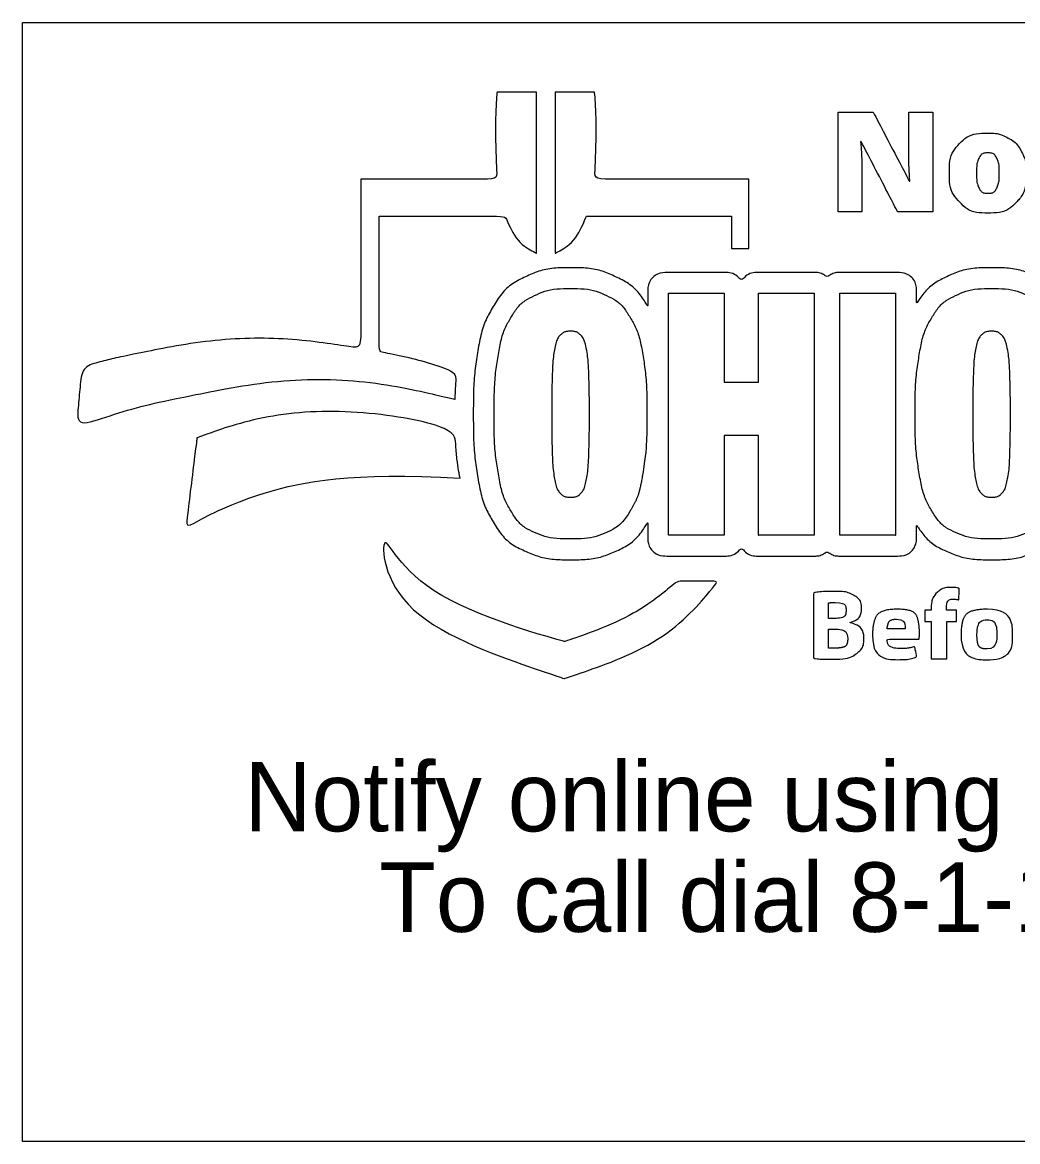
# Model space of a CAD drawing. Extents: x 0 to 34, y 0 to 22.
# Drawn here: x 1.992 to 3.998, y 2.74 to 4.995 of the extents above; entities that cross this region are included whole.
import ezdxf

# ---------------------------------------------------------------- set-up
doc = ezdxf.new("R2010")
doc.units = 0
doc.layers.add('Default', color=7, linetype='Continuous')
doc.layers.add('SH_Data', color=7, linetype='Continuous')

msp = doc.modelspace()

# ---------------------------------------------------------------- linework, layer by layer
at = {"layer": 'Default'}
for points, degree in [([(2.8645, 4.2355), (2.8645, 4.2355), (2.8644, 4.2355), (2.8644, 4.2355), (2.6966, 4.2753), (2.5082, 4.2791), (2.3129, 4.2392), (2.2394, 4.2241), (2.1686, 4.2034), (2.1007, 4.178), (2.1045, 4.2182), (2.1085, 4.2608), (2.1123, 4.301), (2.1442, 4.3099), (2.1765, 4.3182), (2.2095, 4.3249), (2.3719, 4.3581), (2.5295, 4.3609), (2.6744, 4.3379), (2.6744, 4.3379), (2.6744, 4.6788), (2.6744, 4.6788), (2.6744, 4.6788), (2.9488, 4.6788), (2.9488, 4.6788), (2.9438, 4.7876), (2.9488, 4.8545), (2.9488, 4.8545), (2.9488, 4.8545), (3.0286, 4.8545), (3.0286, 4.8545), (3.0286, 4.8545), (3.0286, 4.5298), (3.0286, 4.5298), (3.0286, 4.5298), (2.9887, 4.5504), (2.9652, 4.6045), (2.9652, 4.6045), (2.7111, 4.6045), (2.7111, 4.6045), (2.7111, 4.6045), (2.7111, 4.3314), (2.7111, 4.3314), (2.7654, 4.3211), (2.8178, 4.3071), (2.8678, 4.2896), (2.8661, 4.2729), (2.8651, 4.255), (2.8645, 4.2355)], 3), ([(3.1289, 4.6046), (3.1289, 4.6046), (3.129, 4.6046), (3.129, 4.6046), (3.1056, 4.5506), (3.0657, 4.5299), (3.0657, 4.5299), (3.0657, 4.5299), (3.0657, 4.8545), (3.0657, 4.8545), (3.0657, 4.8545), (3.1454, 4.8545), (3.1454, 4.8545), (3.1454, 4.8545), (3.1504, 4.7876), (3.1454, 4.6788), (3.1454, 4.6788), (3.4564, 4.6788), (3.4564, 4.6788), (3.4564, 4.6788), (3.4564, 4.5391), (3.4564, 4.5391), (3.4564, 4.5391), (3.4216, 4.5391), (3.4216, 4.5391), (3.4216, 4.5391), (3.4216, 4.6046), (3.4216, 4.6046), (3.4216, 4.6046), (3.1289, 4.6046), (3.1289, 4.6046)], 3), ([(3.827, 4.6136), (3.827, 4.6136), (3.827, 4.8142), (3.827, 4.8142), (3.827, 4.8142), (3.7787, 4.8142), (3.7787, 4.8142), (3.7787, 4.8142), (3.7787, 4.7235), (3.7787, 4.7235), (3.7787, 4.7112), (3.7793, 4.695), (3.7806, 4.6748), (3.7806, 4.6748), (3.7798, 4.6748), (3.7798, 4.6748), (3.7798, 4.6748), (3.7068, 4.8142), (3.7068, 4.8142), (3.7068, 4.8142), (3.636, 4.8142), (3.636, 4.8142), (3.636, 4.8142), (3.636, 4.6136), (3.636, 4.6136), (3.636, 4.6136), (3.684, 4.6136), (3.684, 4.6136), (3.684, 4.6136), (3.684, 4.704), (3.684, 4.704), (3.684, 4.7157), (3.6831, 4.7327), (3.6814, 4.7549), (3.6814, 4.7549), (3.6826, 4.7549), (3.6826, 4.7549), (3.6826, 4.7549), (3.7559, 4.6136), (3.7559, 4.6136), (3.7559, 4.6136), (3.827, 4.6136), (3.827, 4.6136)], 3), ([(4.0155, 4.6917), (4.0155, 4.7079), (4.0124, 4.722), (4.006, 4.7341), (3.9996, 4.7462), (3.9906, 4.7555), (3.9789, 4.762), (3.9672, 4.7685), (3.9537, 4.7718), (3.9384, 4.7718), (3.9137, 4.7718), (3.8946, 4.7647), (3.8809, 4.7507), (3.8672, 4.7367), (3.8604, 4.717), (3.8604, 4.6917), (3.8604, 4.6669), (3.8674, 4.6472), (3.8813, 4.6327), (3.8953, 4.6181), (3.914, 4.6109), (3.9376, 4.6109), (3.9622, 4.6109), (3.9813, 4.618), (3.995, 4.6322), (4.0087, 4.6464), (4.0155, 4.6663), (4.0155, 4.6917)], 3), ([(3.9148, 4.6917), (3.9148, 4.705), (3.9166, 4.715), (3.9202, 4.7217), (3.9237, 4.7285), (3.9297, 4.7319), (3.9379, 4.7319), (3.9463, 4.7319), (3.9522, 4.7285), (3.9557, 4.7217), (3.9592, 4.7149), (3.9609, 4.7049), (3.9609, 4.6917), (3.9609, 4.6783), (3.9592, 4.6682), (3.9558, 4.6612), (3.9524, 4.6542), (3.9465, 4.6507), (3.9382, 4.6507), (3.9297, 4.6507), (3.9237, 4.6542), (3.9202, 4.6612), (3.9166, 4.6682), (3.9148, 4.6783), (3.9148, 4.6917)], 3), ([(4.446, 4.455), (4.4144, 4.4855), (4.3702, 4.5002), (4.3111, 4.5002), (4.2002, 4.5002), (4.1366, 4.4444), (4.1306, 4.3429), (4.1242, 4.3742), (4.1149, 4.4001), (4.1019, 4.4218), (4.0855, 4.4493), (4.0634, 4.4697), (4.0361, 4.4826), (4.0108, 4.4946), (3.9804, 4.5007), (3.9456, 4.5007), (3.9108, 4.5007), (3.8804, 4.4946), (3.8552, 4.4826), (3.8304, 4.4709), (3.8102, 4.4527), (3.7943, 4.429), (3.7943, 4.429), (3.7943, 4.4491), (3.7943, 4.4491), (3.7943, 4.4723), (3.7755, 4.4911), (3.7523, 4.4911), (3.7523, 4.4911), (3.64, 4.4911), (3.64, 4.4911), (3.63, 4.4911), (3.6212, 4.4871), (3.614, 4.4814), (3.6068, 4.4871), (3.598, 4.4911), (3.588, 4.4911), (3.588, 4.4911), (3.4757, 4.4911), (3.4757, 4.4911), (3.4615, 4.4911), (3.449, 4.4841), (3.4413, 4.4732), (3.4337, 4.4841), (3.4212, 4.4911), (3.4069, 4.4911), (3.4069, 4.4911), (3.2947, 4.4911), (3.2947, 4.4911), (3.2715, 4.4911), (3.2526, 4.4724), (3.2526, 4.4491), (3.2526, 4.4491), (3.2526, 4.4229), (3.2526, 4.4229), (3.2363, 4.4498), (3.2145, 4.4699), (3.1875, 4.4826), (3.1623, 4.4946), (3.1318, 4.5007), (3.0971, 4.5007), (3.0623, 4.5007), (3.0319, 4.4946), (3.0067, 4.4826), (2.9793, 4.4697), (2.9572, 4.4493), (2.9408, 4.4218), (2.926, 4.3971), (2.9155, 4.3657), (2.9094, 4.3286), (2.9039, 4.2944), (2.901, 4.253), (2.901, 4.2056), (2.901, 4.1582), (2.9039, 4.1167), (2.9094, 4.0825), (2.9155, 4.0454), (2.926, 4.014), (2.9408, 3.9893), (2.9574, 3.9615), (2.98, 3.9411), (3.0076, 3.929), (3.0326, 3.9181), (3.0627, 3.9125), (3.097, 3.9125), (3.1313, 3.9125), (3.1614, 3.9181), (3.1863, 3.929), (3.2137, 3.941), (3.2359, 3.961), (3.2525, 3.9882), (3.2525, 3.9882), (3.2525, 3.962), (3.2525, 3.962), (3.2525, 3.9389), (3.2714, 3.92), (3.2946, 3.92), (3.2946, 3.92), (3.4068, 3.92), (3.4068, 3.92), (3.4211, 3.92), (3.4336, 3.9271), (3.4412, 3.9379), (3.4489, 3.9271), (3.4614, 3.92), (3.4756, 3.92), (3.4756, 3.92), (3.5879, 3.92), (3.5879, 3.92), (3.5979, 3.92), (3.6067, 3.924), (3.6139, 3.9298), (3.6212, 3.924), (3.6299, 3.92), (3.6399, 3.92), (3.6399, 3.92), (3.7522, 3.92), (3.7522, 3.92), (3.7754, 3.92), (3.7942, 3.9388), (3.7942, 3.962), (3.7942, 3.962), (3.7942, 3.9822), (3.7942, 3.9822), (3.8102, 3.9581), (3.831, 3.9401), (3.8562, 3.929), (3.8811, 3.9181), (3.9112, 3.9125), (3.9455, 3.9125), (3.9798, 3.9125), (4.0099, 3.9181), (4.0348, 3.929), (4.0626, 3.9411), (4.0851, 3.9615), (4.1017, 3.9892), (4.1124, 4.0072), (4.1207, 4.0281), (4.1269, 4.0524), (4.1321, 4.0122), (4.1471, 3.9796), (4.1721, 3.9556), (4.2044, 3.9245), (4.2497, 3.9095), (4.3109, 3.9095), (4.3968, 3.9095), (4.4543, 3.9424), (4.4801, 4.0029), (4.4801, 4.0029), (4.4887, 4.0029), (4.4887, 4.0029), (4.4887, 4.0029), (4.4887, 3.9555), (4.4887, 3.9555), (4.4887, 3.9331), (4.5068, 3.9149), (4.5292, 3.9149), (4.5292, 3.9149), (4.653, 3.9149), (4.653, 3.9149), (4.6754, 3.9149), (4.6936, 3.9331), (4.6936, 3.9555), (4.6936, 3.9555), (4.6936, 4.2276), (4.6936, 4.2276), (4.6949, 4.2276), (4.6962, 4.2274), (4.6976, 4.2274), (4.6976, 4.2274), (4.6976, 3.9555), (4.6976, 3.9555), (4.6976, 3.9331), (4.7158, 3.9149), (4.7381, 3.9149), (4.7381, 3.9149), (4.862, 3.9149), (4.862, 3.9149), (4.8768, 3.9149), (4.8897, 3.9231), (4.8967, 3.935), (4.9025, 3.9271), (4.9118, 3.9219), (4.9224, 3.9219), (4.9224, 3.9219), (4.9927, 3.9219), (4.9927, 3.9219), (5.0103, 3.9219), (5.0246, 3.9362), (5.0246, 3.9537), (5.0246, 3.9537), (5.0246, 3.9822), (5.0246, 3.9822), (5.0259, 3.9789), (5.0269, 3.9753), (5.0286, 3.9722), (5.0381, 3.9543), (5.0522, 3.9404), (5.0708, 3.9305), (5.0885, 3.9212), (5.1105, 3.9166), (5.138, 3.9166), (5.1656, 3.9166), (5.1874, 3.9218), (5.205, 3.932), (5.2223, 3.9421), (5.2357, 3.956), (5.2451, 3.9731), (5.2451, 3.9731), (5.2451, 3.9537), (5.2451, 3.9537), (5.2451, 3.9362), (5.2594, 3.9219), (5.277, 3.9219), (5.277, 3.9219), (5.3524, 3.9219), (5.3524, 3.9219), (5.37, 3.9219), (5.3843, 3.9362), (5.3843, 3.9537), (5.3843, 3.9537), (5.3843, 4.0934), (5.3843, 4.0934), (5.3843, 4.1014), (5.3854, 4.105), (5.3852, 4.1054), (5.3867, 4.1063), (5.3933, 4.1074), (5.4006, 4.1067), (5.4029, 4.1065), (5.4051, 4.1061), (5.4076, 4.1057), (5.4091, 4.1054), (5.4106, 4.1059), (5.4121, 4.1058), (5.412, 4.0996), (5.4115, 4.0941), (5.4115, 4.0873), (5.4115, 4.0579), (5.4138, 4.0343), (5.4185, 4.0151), (5.4232, 3.9959), (5.4293, 3.9806), (5.4373, 3.9685), (5.4342, 3.9669), (5.4315, 3.9649), (5.4291, 3.9624), (5.4231, 3.9564), (5.4198, 3.9481), (5.42, 3.9396), (5.4203, 3.9204), (5.4239, 3.9038), (5.4306, 3.8903), (5.4377, 3.8761), (5.4476, 3.8645), (5.4602, 3.8559), (5.4718, 3.8482), (5.485, 3.8428), (5.4998, 3.84), (5.5123, 3.8375), (5.5258, 3.8363), (5.5399, 3.8363), (5.5559, 3.8363), (5.5711, 3.8381), (5.5853, 3.8418), (5.6012, 3.8461), (5.6153, 3.8531), (5.6272, 3.8629), (5.6398, 3.873), (5.6497, 3.8866), (5.6567, 3.9031), (5.6632, 3.9187), (5.6665, 3.9371), (5.6665, 3.958), (5.6665, 3.958), (5.6665, 4.21), (5.6665, 4.21), (5.6665, 4.2276), (5.6523, 4.2418), (5.6347, 4.2418), (5.6347, 4.2418), (5.6347, 4.2417), (5.6347, 4.2417)], 3), ([(3.2171, 4.0108), (3.2049, 3.9906), (3.1891, 3.9761), (3.1694, 3.9675), (3.1496, 3.9589), (3.1255, 3.9545), (3.0969, 3.9545), (3.0682, 3.9545), (3.0441, 3.9588), (3.0244, 3.9675), (3.0047, 3.9761), (2.9889, 3.9906), (2.9768, 4.0108), (2.9646, 4.031), (2.956, 4.0572), (2.9508, 4.0893), (2.9455, 4.1213), (2.9429, 4.1601), (2.9429, 4.2056), (2.9429, 4.251), (2.9456, 4.2898), (2.9508, 4.3219), (2.956, 4.3539), (2.9646, 4.3801), (2.9768, 4.4003), (2.9889, 4.4206), (3.0047, 4.4353), (3.0244, 4.4447), (3.0442, 4.4541), (3.0683, 4.4587), (3.0969, 4.4587), (3.1254, 4.4587), (3.1496, 4.454), (3.1694, 4.4447), (3.1891, 4.4354), (3.2049, 4.4206), (3.2171, 4.4003), (3.2292, 4.3801), (3.2378, 4.3539), (3.2431, 4.3219), (3.2482, 4.2898), (3.2509, 4.251), (3.2509, 4.2056), (3.2509, 4.1601), (3.2482, 4.1213), (3.2431, 4.0893)], 3), ([(3.4755, 3.962), (3.4755, 3.962), (3.4755, 4.1627), (3.4755, 4.1627), (3.4755, 4.1627), (3.4067, 4.1627), (3.4067, 4.1627), (3.4067, 4.1627), (3.4067, 3.962), (3.4067, 3.962), (3.4067, 3.962), (3.2945, 3.962), (3.2945, 3.962), (3.2945, 3.962), (3.2945, 4.4492), (3.2945, 4.4492), (3.2945, 4.4492), (3.4067, 4.4492), (3.4067, 4.4492), (3.4067, 4.4492), (3.4067, 4.2705), (3.4067, 4.2705), (3.4067, 4.2705), (3.4755, 4.2705), (3.4755, 4.2705), (3.4755, 4.2705), (3.4755, 4.4492), (3.4755, 4.4492), (3.4755, 4.4492), (3.5878, 4.4492), (3.5878, 4.4492), (3.5878, 4.4492), (3.5878, 3.962), (3.5878, 3.962)], 3), ([(3.6397, 3.962), (3.6397, 3.962), (3.6397, 4.4492), (3.6397, 4.4492), (3.6397, 4.4492), (3.752, 4.4492), (3.752, 4.4492), (3.752, 4.4492), (3.752, 3.962), (3.752, 3.962)], 3), ([(4.0654, 4.0108), (4.0533, 3.9906), (4.0375, 3.9761), (4.0177, 3.9675), (3.998, 3.9589), (3.9738, 3.9545), (3.9452, 3.9545), (3.9166, 3.9545), (3.8924, 3.9588), (3.8728, 3.9675), (3.8531, 3.9761), (3.8372, 3.9906), (3.8251, 4.0108), (3.813, 4.031), (3.8044, 4.0572), (3.7991, 4.0893), (3.7938, 4.1213), (3.7913, 4.1601), (3.7913, 4.2056), (3.7913, 4.251), (3.7939, 4.2898), (3.7991, 4.3219), (3.8044, 4.3539), (3.813, 4.3801), (3.8251, 4.4003), (3.8372, 4.4206), (3.8531, 4.4353), (3.8728, 4.4447), (3.8925, 4.4541), (3.9167, 4.4587), (3.9452, 4.4587), (3.9737, 4.4587), (3.998, 4.454), (4.0177, 4.4447), (4.0375, 4.4354), (4.0533, 4.4206), (4.0654, 4.4003), (4.0775, 4.3801), (4.0861, 4.3539), (4.0914, 4.3219), (4.0966, 4.2898), (4.0992, 4.251), (4.0992, 4.2056), (4.0992, 4.1601), (4.0966, 4.1213), (4.0914, 4.0893)], 3), ([(3.1286, 4.3386), (3.1312, 4.3259), (3.1329, 4.3087), (3.1337, 4.2871), (3.1345, 4.2655), (3.1349, 4.2383), (3.1349, 4.2056), (3.1349, 4.1728), (3.1345, 4.1457), (3.1337, 4.1241), (3.1329, 4.1025), (3.1313, 4.0853), (3.1286, 4.0726), (3.126, 4.0599), (3.1222, 4.051), (3.1172, 4.046), (3.1122, 4.041), (3.1055, 4.0385), (3.097, 4.0385), (3.0885, 4.0385), (3.0818, 4.041), (3.0767, 4.046), (3.0717, 4.051), (3.0679, 4.0599), (3.0653, 4.0726), (3.0628, 4.0853), (3.061, 4.1025), (3.0602, 4.1241), (3.0594, 4.1457), (3.059, 4.1728), (3.059, 4.2056), (3.059, 4.2383), (3.0594, 4.2655), (3.0602, 4.2871), (3.061, 4.3087), (3.0627, 4.3259), (3.0653, 4.3386), (3.0678, 4.3513), (3.0716, 4.3602), (3.0767, 4.3652), (3.0818, 4.3701), (3.0885, 4.3727), (3.097, 4.3727), (3.1055, 4.3727), (3.1121, 4.3701), (3.1172, 4.3652), (3.1222, 4.3602), (3.126, 4.3513), (3.1286, 4.3386)], 3), ([(3.9771, 4.3386), (3.9796, 4.3259), (3.9814, 4.3087), (3.9821, 4.2871), (3.9829, 4.2655), (3.9833, 4.2383), (3.9833, 4.2056), (3.9833, 4.1728), (3.9829, 4.1457), (3.9821, 4.1241), (3.9814, 4.1025), (3.9797, 4.0853), (3.9771, 4.0726), (3.9744, 4.0599), (3.9706, 4.051), (3.9656, 4.046), (3.9606, 4.041), (3.9539, 4.0385), (3.9454, 4.0385), (3.9369, 4.0385), (3.9303, 4.041), (3.9252, 4.046), (3.9202, 4.051), (3.9164, 4.0599), (3.9137, 4.0726), (3.9112, 4.0853), (3.9094, 4.1025), (3.9087, 4.1241), (3.9079, 4.1457), (3.9075, 4.1728), (3.9075, 4.2056), (3.9075, 4.2383), (3.9079, 4.2655), (3.9087, 4.2871), (3.9094, 4.3087), (3.9111, 4.3259), (3.9137, 4.3386), (3.9163, 4.3513), (3.9201, 4.3602), (3.9252, 4.3652), (3.9303, 4.3701), (3.9369, 4.3727), (3.9454, 4.3727), (3.9539, 4.3727), (3.9605, 4.3701), (3.9656, 4.3652), (3.9706, 4.3602), (3.9744, 4.3513), (3.9771, 4.3386)], 3), ([(2.8743, 4.0768), (2.6551, 4.0893), (2.4573, 4.0506), (2.3218, 3.9774), (2.3218, 3.9774), (2.3437, 4.1559), (2.3437, 4.1559), (2.3437, 4.1559), (2.3437, 4.158), (2.3437, 4.158), (2.479, 4.2066), (2.6643, 4.2171), (2.8644, 4.181), (2.8653, 4.146), (2.8676, 4.1153), (2.8719, 4.0892), (2.8726, 4.0849), (2.8735, 4.0809), (2.8743, 4.0768)], 3), ([(3.2431, 4.0893), (3.2378, 4.0572), (3.2292, 4.031), (3.2171, 4.0108)], 2), ([(3.0844, 3.7477), (3.0844, 3.7477), (3.2135, 3.7874), (3.312, 3.8693), (3.312, 3.8693), (3.3947, 3.8693), (3.3947, 3.8693), (3.2889, 3.7428), (3.0842, 3.6731), (3.0842, 3.6731), (3.0842, 3.6731), (2.7221, 3.7963), (2.7119, 4.013), (2.7682, 3.8307), (3.0844, 3.7477), (3.0844, 3.7477)], 3), ([(3.5878, 3.962), (3.5878, 3.962), (3.4755, 3.962), (3.4755, 3.962)], 2), ([(3.752, 3.962), (3.752, 3.962), (3.6397, 3.962), (3.6397, 3.962)], 2), ([(3.8364, 3.8471), (3.8364, 3.8471), (3.8364, 3.8471), (3.8364, 3.8471), (3.8442, 3.8543), (3.8549, 3.8569), (3.8639, 3.8569), (3.8708, 3.8569), (3.8761, 3.8561), (3.8804, 3.8549), (3.8804, 3.8549), (3.8791, 3.8316), (3.8791, 3.8316), (3.8765, 3.8324), (3.8733, 3.833), (3.8692, 3.833), (3.859, 3.833), (3.8547, 3.8252), (3.8547, 3.8157), (3.8547, 3.8157), (3.8547, 3.8107), (3.8547, 3.8107), (3.8547, 3.8107), (3.8746, 3.8107), (3.8746, 3.8107), (3.8746, 3.8107), (3.8746, 3.7884), (3.8746, 3.7884), (3.8746, 3.7884), (3.8549, 3.7884), (3.8549, 3.7884), (3.8549, 3.7884), (3.8549, 3.7132), (3.8549, 3.7132), (3.8549, 3.7132), (3.8238, 3.7132), (3.8238, 3.7132), (3.8238, 3.7132), (3.8238, 3.7884), (3.8238, 3.7884), (3.8238, 3.7884), (3.8108, 3.7884), (3.8108, 3.7884), (3.8108, 3.7884), (3.8108, 3.8107), (3.8108, 3.8107), (3.8108, 3.8107), (3.8238, 3.8107), (3.8238, 3.8107), (3.8238, 3.8107), (3.8238, 3.8145), (3.8238, 3.8145), (3.8238, 3.8262), (3.8274, 3.8391), (3.8364, 3.8471)], 3), ([(3.6607, 3.786), (3.6762, 3.7915), (3.6833, 3.8027), (3.6833, 3.8147), (3.6833, 3.8267), (3.6764, 3.836), (3.6669, 3.841), (3.6569, 3.8467), (3.6453, 3.8486), (3.6264, 3.8486), (3.611, 3.8486), (3.5945, 3.8474), (3.5864, 3.8458), (3.5864, 3.8458), (3.5864, 3.7138), (3.5864, 3.7138), (3.5933, 3.7129), (3.6046, 3.7119), (3.6199, 3.7119), (3.6471, 3.7119), (3.6639, 3.7163), (3.6738, 3.724), (3.6823, 3.7307), (3.688, 3.7403), (3.688, 3.7525), (3.688, 3.7699), (3.6764, 3.7815), (3.6607, 3.7857)], 3), ([(3.6302, 3.8264), (3.6442, 3.8264), (3.6522, 3.821), (3.6522, 3.8109), (3.6522, 3.8007), (3.6434, 3.7944), (3.6272, 3.7944), (3.6272, 3.7944), (3.617, 3.7944), (3.617, 3.7944), (3.617, 3.7944), (3.617, 3.8256), (3.617, 3.8256), (3.617, 3.8256), (3.617, 3.8256), (3.617, 3.8256)], 3), ([(3.617, 3.8256), (3.6197, 3.826), (3.6235, 3.8264), (3.6302, 3.8264)], 2), ([(3.7557, 3.8128), (3.7211, 3.8128), (3.7055, 3.7855), (3.7055, 3.7608)], 2), ([(3.7557, 3.8128), (3.7557, 3.8128), (3.7556, 3.8128), (3.7556, 3.8128)], 2), ([(3.7556, 3.8128), (3.7556, 3.8128), (3.7557, 3.8128), (3.7557, 3.8128)], 2), ([(3.7557, 3.8128), (3.7557, 3.8128), (3.7557, 3.8128), (3.7557, 3.8128)], 2), ([(3.8, 3.7642), (3.8, 3.7883), (3.7878, 3.8128), (3.7557, 3.8128)], 2), ([(3.8839, 3.7612), (3.8839, 3.7298), (3.9063, 3.711), (3.9353, 3.711), (3.962, 3.711), (3.9878, 3.7273), (3.9878, 3.763), (3.9878, 3.7923), (3.9675, 3.8128), (3.937, 3.8128)], 3), ([(3.937, 3.8128), (3.905, 3.8128), (3.8839, 3.7927), (3.8839, 3.7612)], 2), ([(3.754, 3.7927), (3.7682, 3.7927), (3.7715, 3.7804), (3.7715, 3.773), (3.7715, 3.773), (3.7348, 3.773), (3.7348, 3.773)], 3), ([(3.7348, 3.773), (3.7356, 3.7812), (3.7409, 3.7927), (3.754, 3.7927)], 2), ([(3.9159, 3.762), (3.9159, 3.7764), (3.9214, 3.7913), (3.9362, 3.7913), (3.9502, 3.7913), (3.956, 3.7766), (3.956, 3.762), (3.956, 3.7444), (3.9482, 3.7327), (3.9362, 3.7327)], 3), ([(3.617, 3.7347), (3.617, 3.7347), (3.617, 3.7727), (3.617, 3.7727), (3.617, 3.7727), (3.6276, 3.7727), (3.6276, 3.7727), (3.643, 3.7727), (3.6555, 3.7673), (3.6555, 3.7537)], 3), ([(3.6607, 3.7857), (3.6607, 3.7858), (3.6607, 3.786), (3.6607, 3.786)], 2), ([(3.6555, 3.7537), (3.6555, 3.7401), (3.6431, 3.7344), (3.6291, 3.7344)], 2), ([(3.7055, 3.7608), (3.7055, 3.7303), (3.7248, 3.7112), (3.7586, 3.7112), (3.7719, 3.7112), (3.7844, 3.7131), (3.7945, 3.7172), (3.7945, 3.7172), (3.7904, 3.7377), (3.7904, 3.7377), (3.7821, 3.735), (3.7735, 3.7337), (3.7629, 3.7337), (3.7485, 3.7337), (3.7359, 3.7396), (3.7349, 3.7522), (3.7349, 3.7522), (3.799, 3.7522), (3.799, 3.7522), (3.7994, 3.7544), (3.8, 3.759), (3.8, 3.7642)], 3), ([(3.9362, 3.7327), (3.923, 3.7327), (3.9159, 3.7452), (3.9159, 3.762)], 2), ([(3.6291, 3.7344), (3.6238, 3.7344), (3.6202, 3.7344), (3.617, 3.7347)], 2)]:
    msp.add_open_spline(points, degree=degree, dxfattribs=at)
at = {"layer": 'SH_Data'}
msp.add_lwpolyline([(1.9922, 4.9949), (6.8439, 4.9949), (6.8439, 2.7404), (1.9922, 2.7404)], close=True, dxfattribs=at)

# ---------------------------------------------------------------- texts
for s, p in [('Notify online using ', (2.4397, 3.3654)), ('To call dial 8-1-1 or 800-362-2764', (2.7111, 3.1629))]:
    msp.add_text(s, height=0.14, dxfattribs=at).set_placement(p)

doc.saveas('drawing.dxf')
